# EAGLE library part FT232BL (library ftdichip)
USB UART 2nd Generation USB UART (USB <-> Serial) Controller
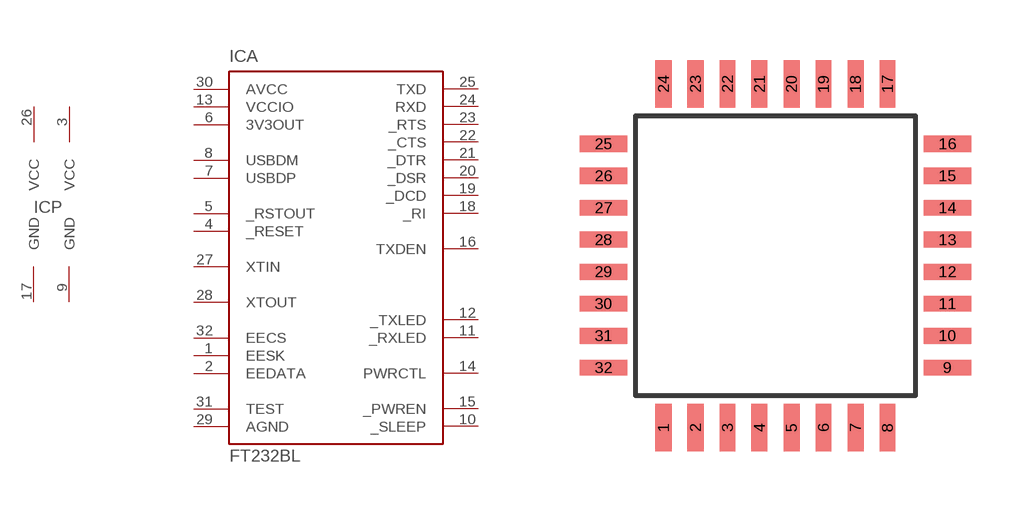
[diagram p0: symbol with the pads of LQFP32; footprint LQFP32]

Designator prefix IC; gates A=FT232BL P=2VCC2GND

## FT232BL  [LQFP32]
1  A:EESK  out
2  A:EEDATA
3  P:VCC  pwr
4  A:_RESET  in
5  A:_RSTOUT  out
6  A:3V3OUT  out
7  A:USBDP
8  A:USBDM
9  P:GND  pwr
10  A:_SLEEP  out
11  A:_RXLED  oc
12  A:_TXLED  oc
13  A:VCCIO  pwr
14  A:PWRCTL  in
15  A:_PWREN  out
16  A:TXDEN  out
17  P:GND  pwr
18  A:_RI  in
19  A:_DCD  in
20  A:_DSR  in
21  A:_DTR  out
22  A:_CTS  in
23  A:_RTS  out
24  A:RXD  in
25  A:TXD  out
26  P:VCC  pwr
27  A:XTIN  in
28  A:XTOUT  out
29  A:AGND  pwr
30  A:AVCC  pwr
31  A:TEST  in
32  A:EECS

## Footprint LQFP32 (pad centres in mm)
LQFP-32 package 7x7 mm case, 0.8 mm lead pitch
smd 0.4 x 1.2: 1 -2.8,-4.3; 2 -2,-4.3; 3 -1.2,-4.3; 4 -0.4,-4.3; 5 0.4,-4.3; 6 1.2,-4.3; 7 2,-4.3; 8 2.8,-4.3; 17 2.8,4.3; 18 2,4.3; 19 1.2,4.3; 20 0.4,4.3; 21 -0.4,4.3; 22 -1.2,4.3; 23 -2,4.3; 24 -2.8,4.3
smd 1.2 x 0.4: 9 4.3,-2.8; 10 4.3,-2; 11 4.3,-1.2; 12 4.3,-0.4; 13 4.3,0.4; 14 4.3,1.2; 15 4.3,2; 16 4.3,2.8; 25 -4.3,2.8; 26 -4.3,2; 27 -4.3,1.2; 28 -4.3,0.4; 29 -4.3,-0.4; 30 -4.3,-1.2; 31 -4.3,-2; 32 -4.3,-2.8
